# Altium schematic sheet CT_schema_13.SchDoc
size 741 x 377 mm
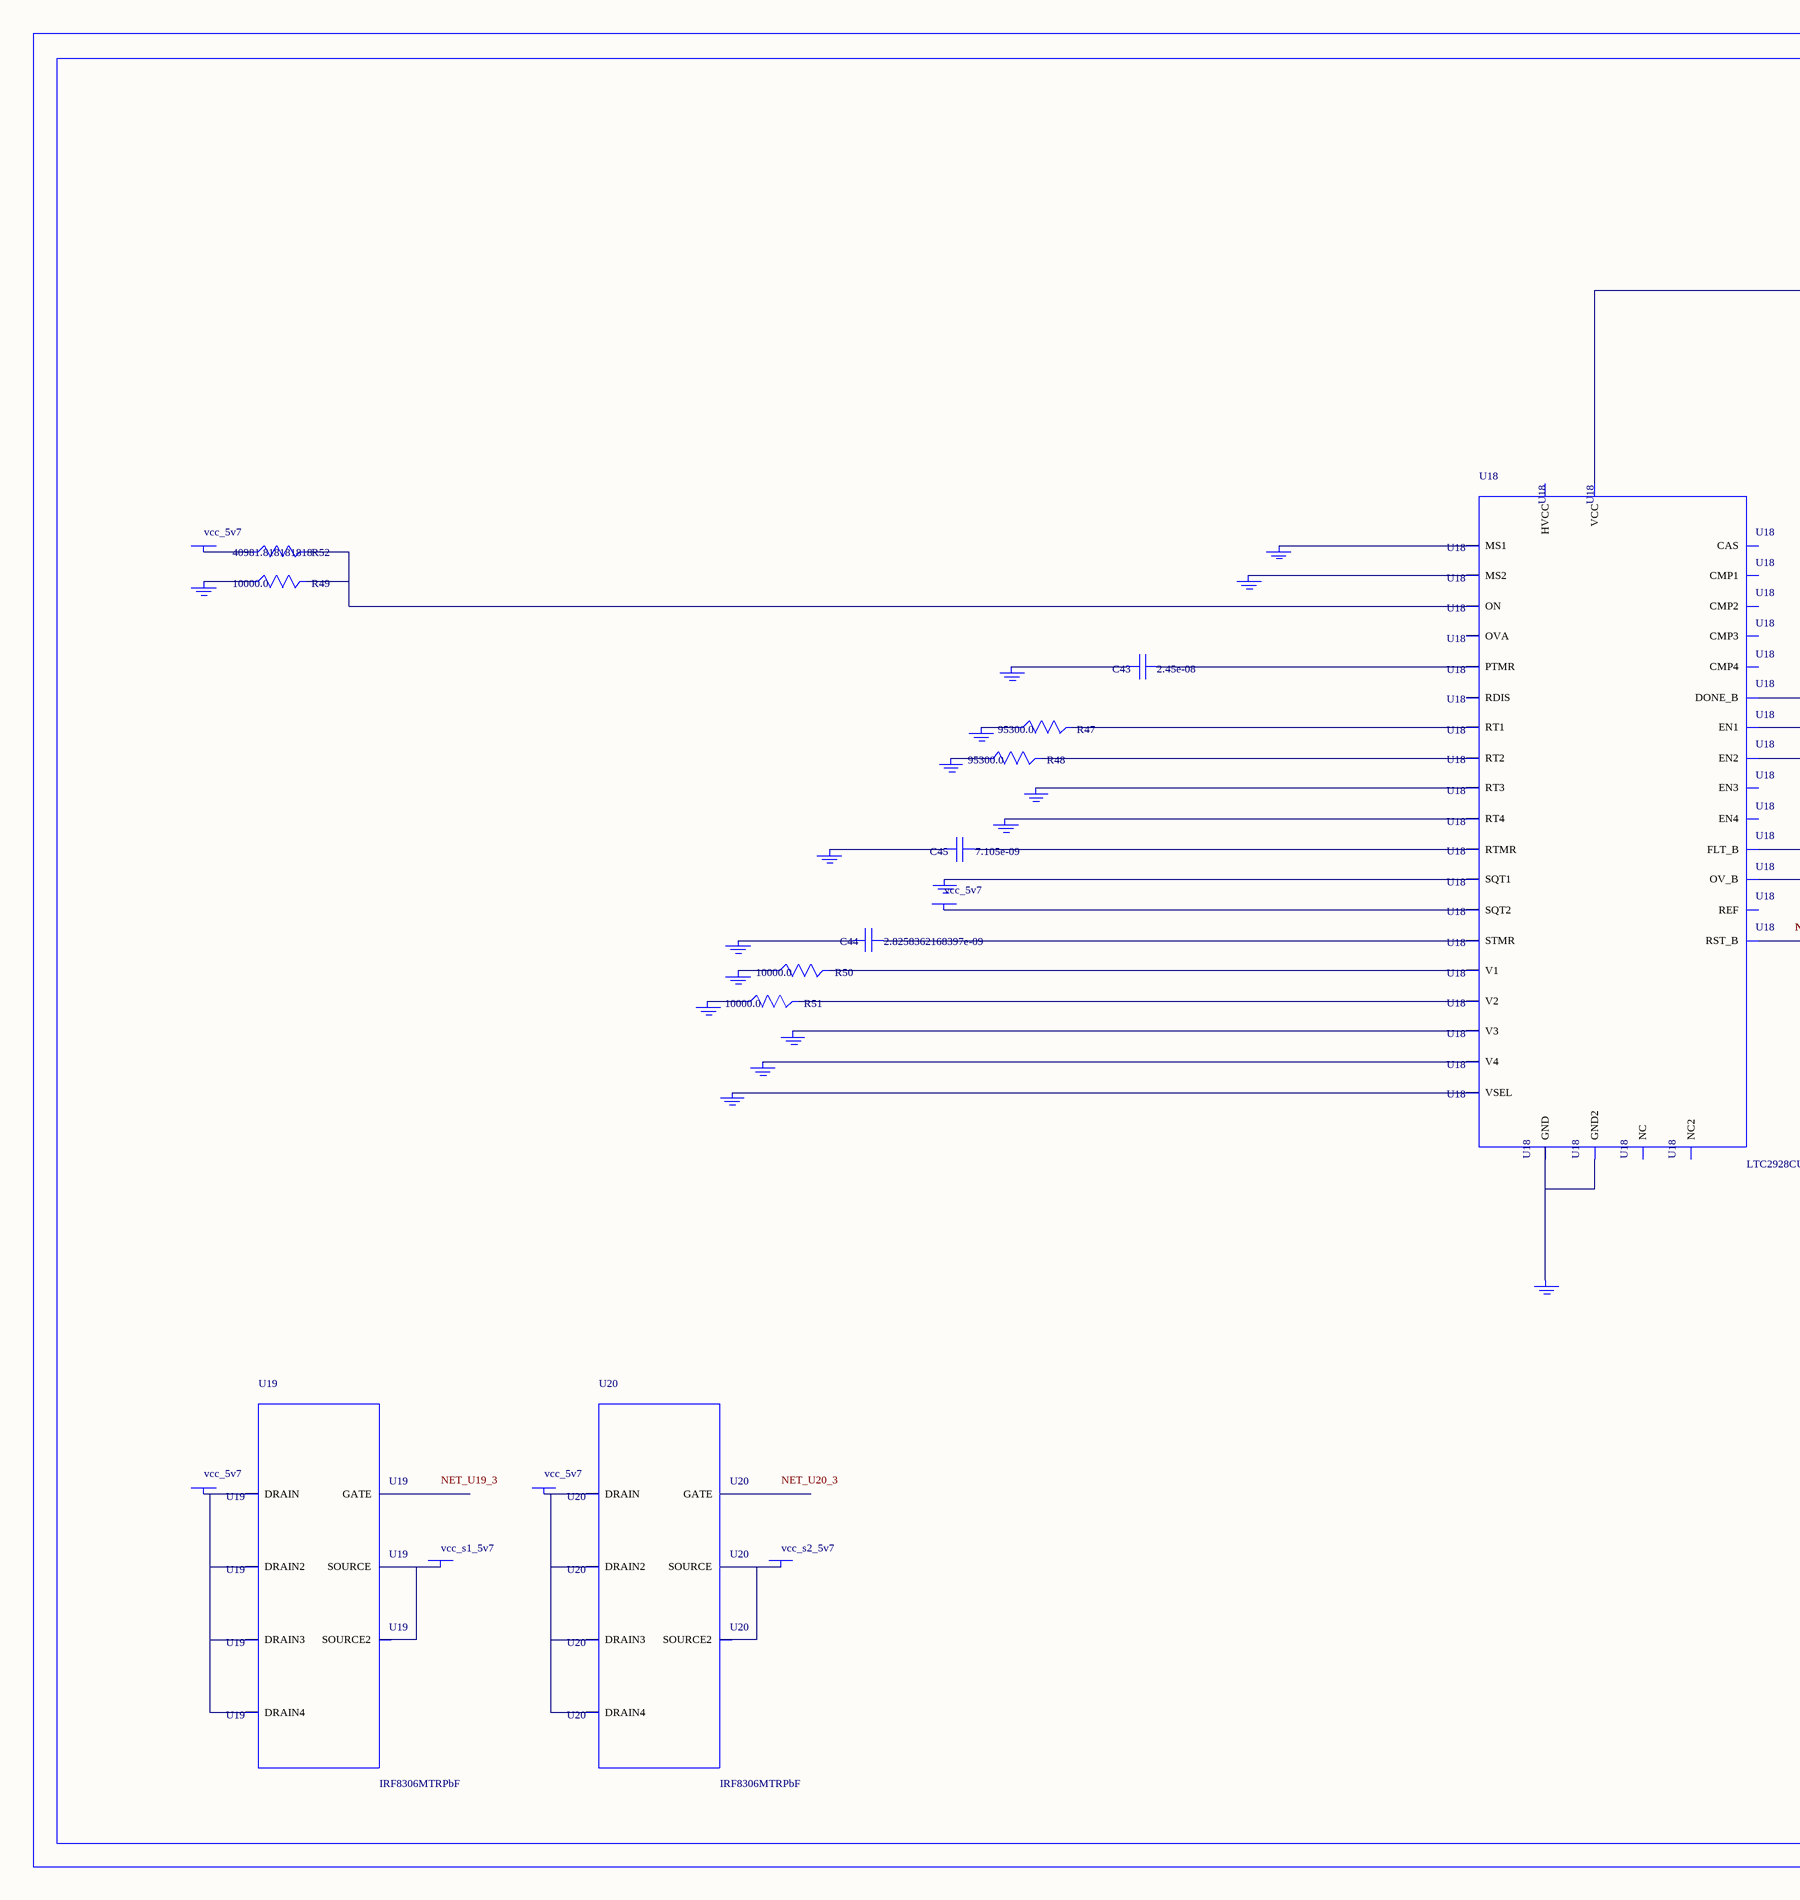
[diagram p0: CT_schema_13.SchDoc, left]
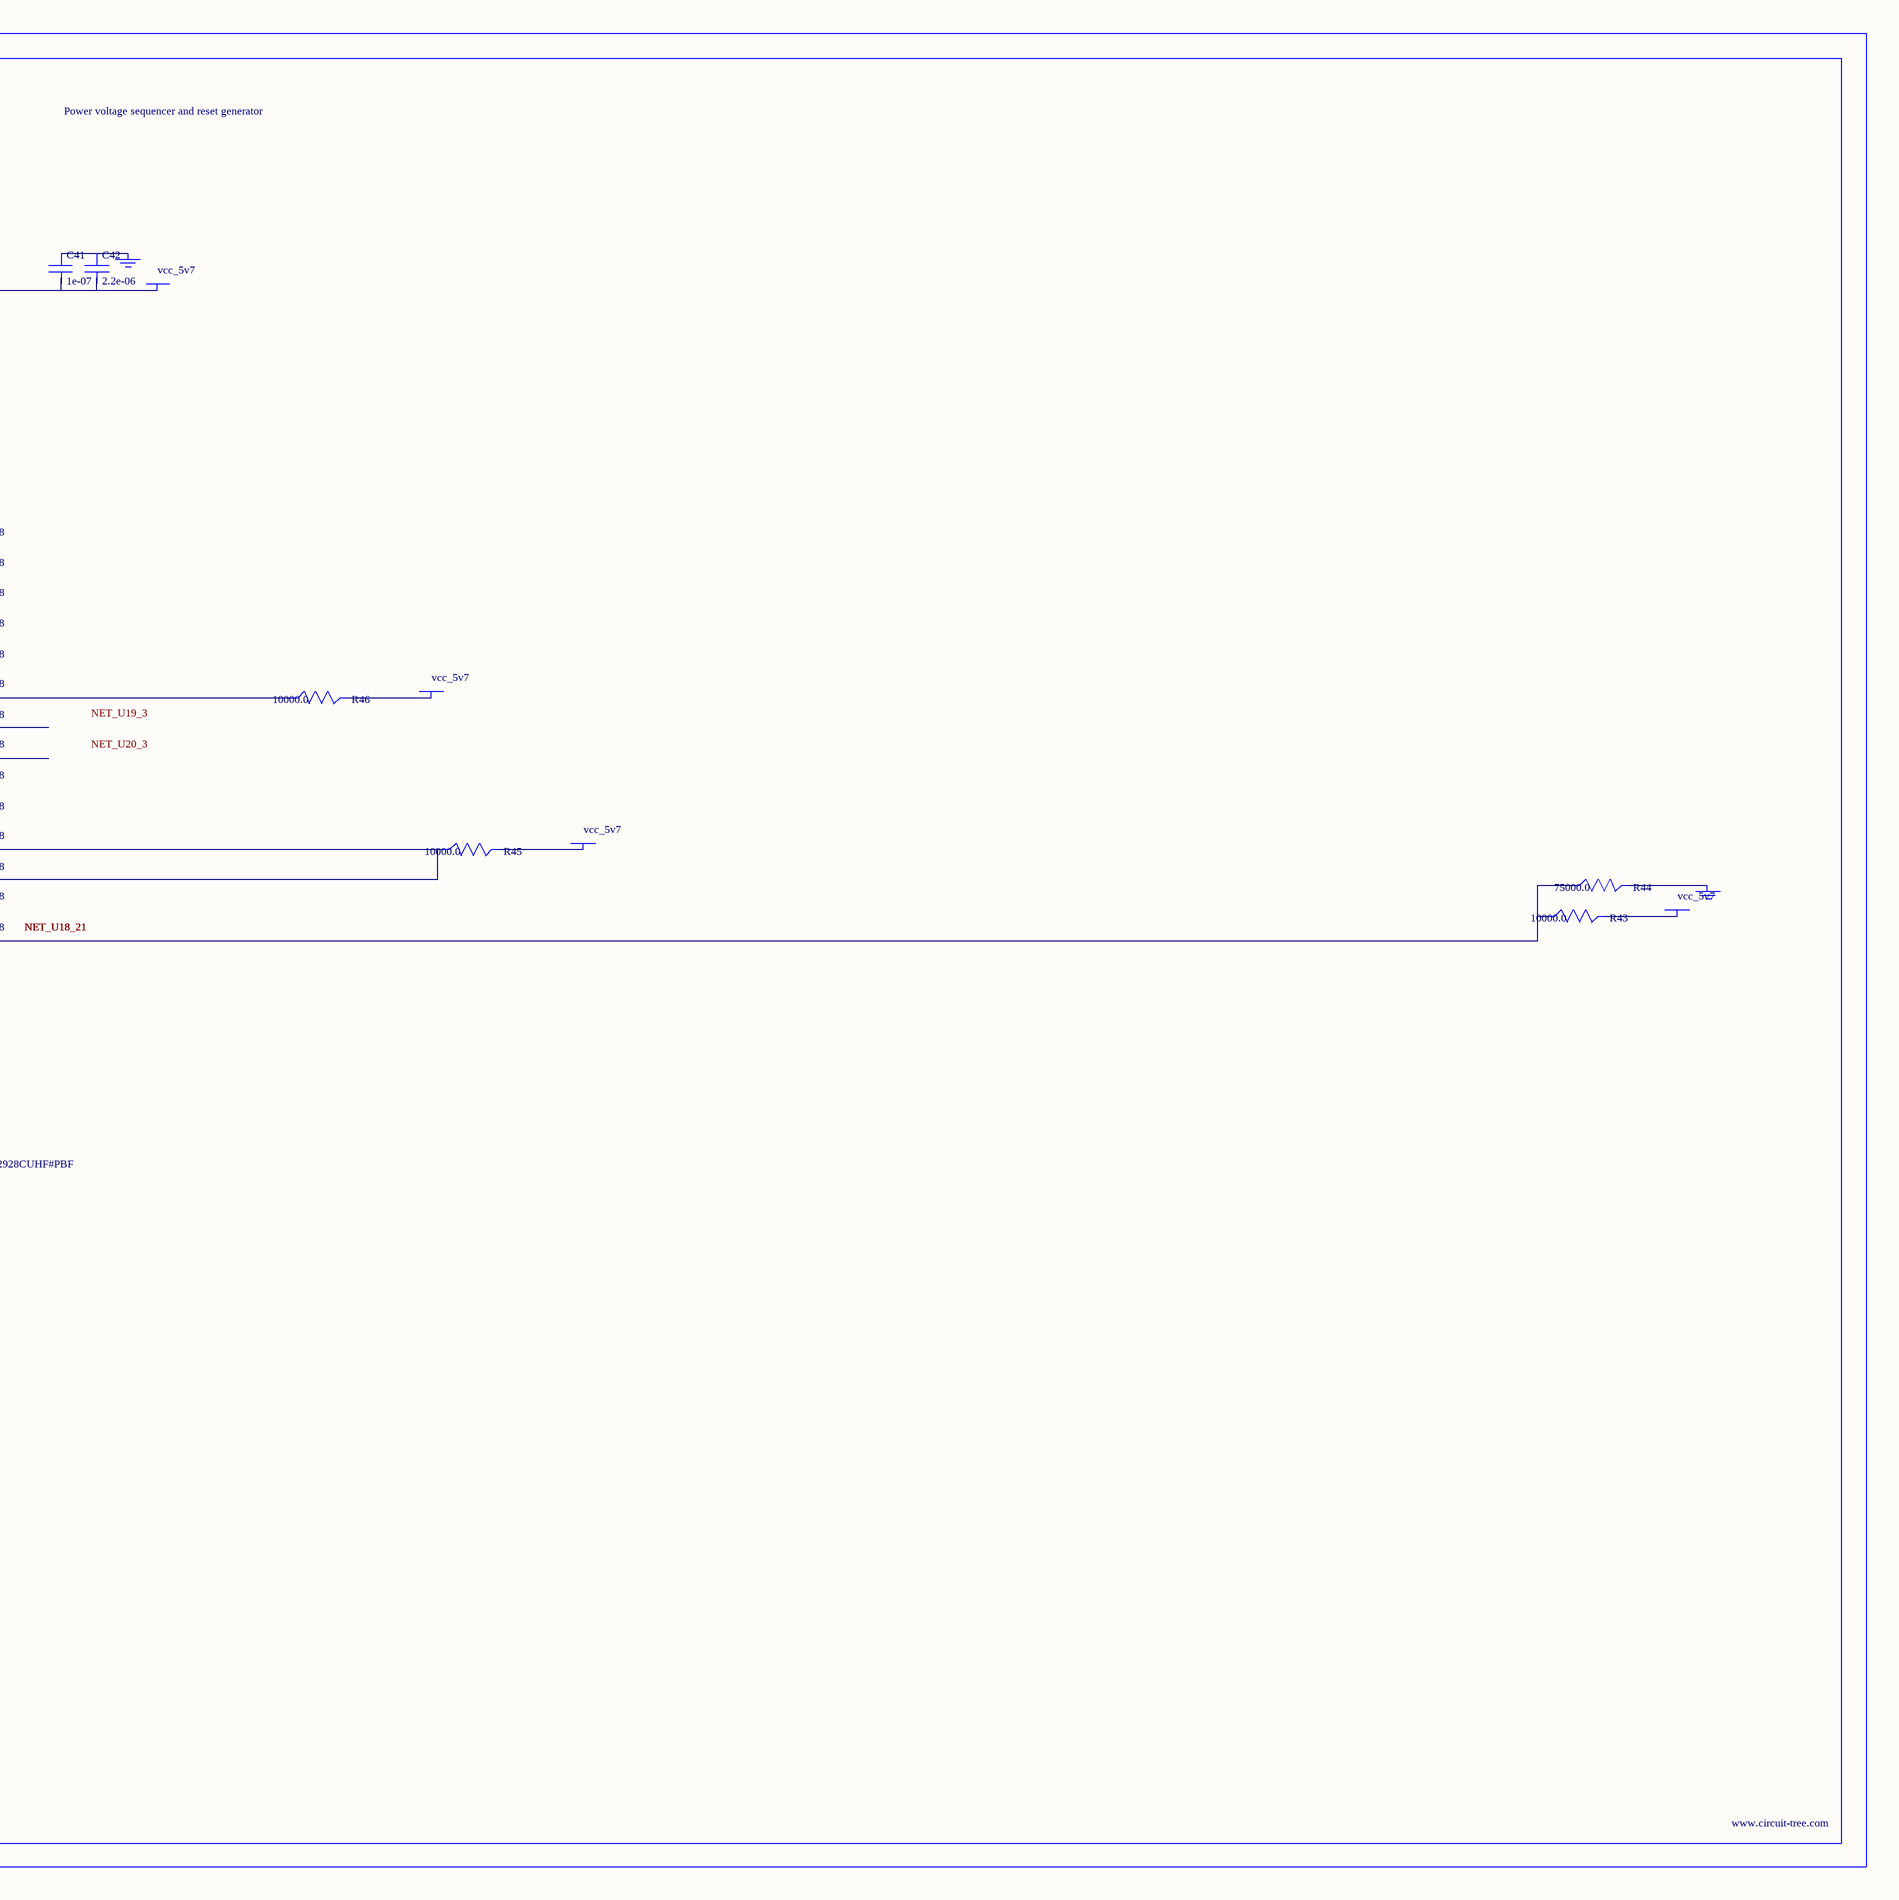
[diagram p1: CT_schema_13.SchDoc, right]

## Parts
BORDER12  (no value)
C41  1e-07  [C0402]
C42  2.2e-06  [C0603]
C43  2.45e-08  [R0603]
C44  2.8258362168397e-09  [R0603]
C45  7.105e-09  [R0603]
GND_INSTANCE_12_0  (no value)
GND_INSTANCE_12_1  (no value)
GND_INSTANCE_12_2  (no value)
GND_INSTANCE_12_3  (no value)
GND_INSTANCE_12_4  (no value)
GND_INSTANCE_12_5  (no value)
GND_INSTANCE_12_6  (no value)
GND_INSTANCE_12_7  (no value)
GND_INSTANCE_12_8  (no value)
GND_INSTANCE_12_9  (no value)
GND_INSTANCE_12_10  (no value)
GND_INSTANCE_12_11  (no value)
GND_INSTANCE_12_12  (no value)
GND_INSTANCE_12_13  (no value)
GND_INSTANCE_12_14  (no value)
GND_INSTANCE_12_15  (no value)
GND_INSTANCE_12_16  (no value)
GND_INSTANCE_12_17  (no value)
GND_INSTANCE_12_18  (no value)
POWER_INSTANCE_12_0  vcc_5v7
POWER_INSTANCE_12_1  vcc_5v7
POWER_INSTANCE_12_2  vcc_5v7
POWER_INSTANCE_12_3  vcc_5v7
POWER_INSTANCE_12_4  vcc_5v7
POWER_INSTANCE_12_5  vcc_5v7
POWER_INSTANCE_12_6  vcc_5v7
POWER_INSTANCE_12_7  vcc_s1_5v7
POWER_INSTANCE_12_8  vcc_5v7
POWER_INSTANCE_12_9  vcc_s2_5v7
R43  10000.0  [R0603]
R44  75000.0  [R0603]
R45  10000.0  [R0603]
R46  10000.0  [R0603]
R47  95300.0  [R0603]
R48  95300.0  [R0603]
R49  10000.0  [R0603]
R50  10000.0  [R0603]
R51  10000.0  [R0603]
R52  40981.818181818  [R0603]
U18  LTC2928CUHF#PBF  [QFN-38_UHF]
U19  IRF8306MTRPbF  [IRF8306MTRPBF]
U20  IRF8306MTRPbF  [IRF8306MTRPBF]

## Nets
NetC41_1: C41.1 C42.1 GND_INSTANCE_12_10.0(GND)
NetC41_2: C41.2 C42.2 POWER_INSTANCE_12_5.0(PWR) U18.22(VCC)
NetC43_1: C43.1 U18.27(PTMR)
NetC43_2: C43.2 GND_INSTANCE_12_13.0(GND)
NetC44_1: C44.1 U18.26(STMR)
NetC44_2: C44.2 GND_INSTANCE_12_12.0(GND)
NetC45_1: C45.1 U18.28(RTMR)
NetC45_2: C45.2 GND_INSTANCE_12_14.0(GND)
NetGND_INSTANCE_12_0_0: GND_INSTANCE_12_0.0(GND) R50.1
NetGND_INSTANCE_12_1_0: GND_INSTANCE_12_1.0(GND) R47.1
NetGND_INSTANCE_12_2_0: GND_INSTANCE_12_2.0(GND) R48.1
NetGND_INSTANCE_12_3_0: GND_INSTANCE_12_3.0(GND) U18.8(RT3)
NetGND_INSTANCE_12_4_0: GND_INSTANCE_12_4.0(GND) U18.9(RT4)
NetGND_INSTANCE_12_5_0: GND_INSTANCE_12_5.0(GND) U18.10(SQT1)
NetGND_INSTANCE_12_6_0: GND_INSTANCE_12_6.0(GND) U18.12(MS1)
NetGND_INSTANCE_12_7_0: GND_INSTANCE_12_7.0(GND) U18.13(MS2)
NetGND_INSTANCE_12_8_0: GND_INSTANCE_12_8.0(GND) R49.1
NetGND_INSTANCE_12_9_0: GND_INSTANCE_12_9.0(GND) R44.2
NetGND_INSTANCE_12_11_0: GND_INSTANCE_12_11.0(GND) U18.25(VSEL)
NetGND_INSTANCE_12_15_0: GND_INSTANCE_12_15.0(GND) U18.30(V4)
NetGND_INSTANCE_12_16_0: GND_INSTANCE_12_16.0(GND) U18.32(V3)
NetGND_INSTANCE_12_17_0: GND_INSTANCE_12_17.0(GND) R51.1
NetGND_INSTANCE_12_18_0: GND_INSTANCE_12_18.0(GND) U18.24(GND) U18.39(GND2)
NetPOWER_INSTANCE_12_0_0: POWER_INSTANCE_12_0.0(PWR) U18.11(SQT2)
NetPOWER_INSTANCE_12_1_0: POWER_INSTANCE_12_1.0(PWR) R52.1
NetPOWER_INSTANCE_12_2_0: POWER_INSTANCE_12_2.0(PWR) R46.2
NetPOWER_INSTANCE_12_3_0: POWER_INSTANCE_12_3.0(PWR) R45.2
NetPOWER_INSTANCE_12_4_0: POWER_INSTANCE_12_4.0(PWR) R43.2
NetPOWER_INSTANCE_12_6_0: POWER_INSTANCE_12_6.0(PWR) U19.1(DRAIN) U19.2(DRAIN2) U19.6(DRAIN3) U19.7(DRAIN4)
NetPOWER_INSTANCE_12_7_0: POWER_INSTANCE_12_7.0(PWR) U19.4(SOURCE) U19.5(SOURCE2)
NetPOWER_INSTANCE_12_8_0: POWER_INSTANCE_12_8.0(PWR) U20.1(DRAIN) U20.2(DRAIN2) U20.6(DRAIN3) U20.7(DRAIN4)
NetPOWER_INSTANCE_12_9_0: POWER_INSTANCE_12_9.0(PWR) U20.4(SOURCE) U20.5(SOURCE2)
NetR43_1: R43.1 R44.1 U18.21(RST_B)
NetR45_1: R45.1 U18.19(FLT_B) U18.20(OV_B)
NetR46_1: R46.1 U18.18(DONE_B)
NetR47_2: R47.2 U18.6(RT1)
NetR48_2: R48.2 U18.7(RT2)
NetR49_2: R49.2 R52.2 U18.16(ON)
NetR50_2: R50.2 U18.3(V1)
NetR51_2: R51.2 U18.38(V2)

Not connected (* = marked no-connect by the designer): U18 1(OVA) 2(EN1) 4(NC) 5(REF) 14(RDIS) 15(CAS) 17(NC2) 23(HVCC) 29(EN4) 31(EN3) 33(CMP3) 34(CMP4) 35(CMP1) 36(CMP2) 37(EN2); U19 3(GATE); U20 3(GATE)

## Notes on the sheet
- Labels drawn without touching a wire or pin: NET_U19_3, NET_U20_3

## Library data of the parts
BORDER12 = BORDER_PAGE12
C41 = C0402C104K3RACTU
C42 = GRM188R61H225KE1115D
C43 = C43
C44 = C44
C45 = C45
GND_INSTANCE_12_0-GND_INSTANCE_12_18 = GND
POWER_INSTANCE_12_0-POWER_INSTANCE_12_9 = PWR
R43 R45 R46 R49-R51 = RC0603JR-0710KL
R44 = RC0603JR-0775KL
R47 R48 = RC0603FR-0795K3L
R52 = R52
